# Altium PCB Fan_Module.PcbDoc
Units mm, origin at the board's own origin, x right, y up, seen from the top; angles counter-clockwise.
Board outline 101.5 x 99.19 mm, 2 copper layers (Top Layer, Bottom Layer), stack 1.671 mm thick; 41 components, 31 nets, 143 pads, 0 vias.
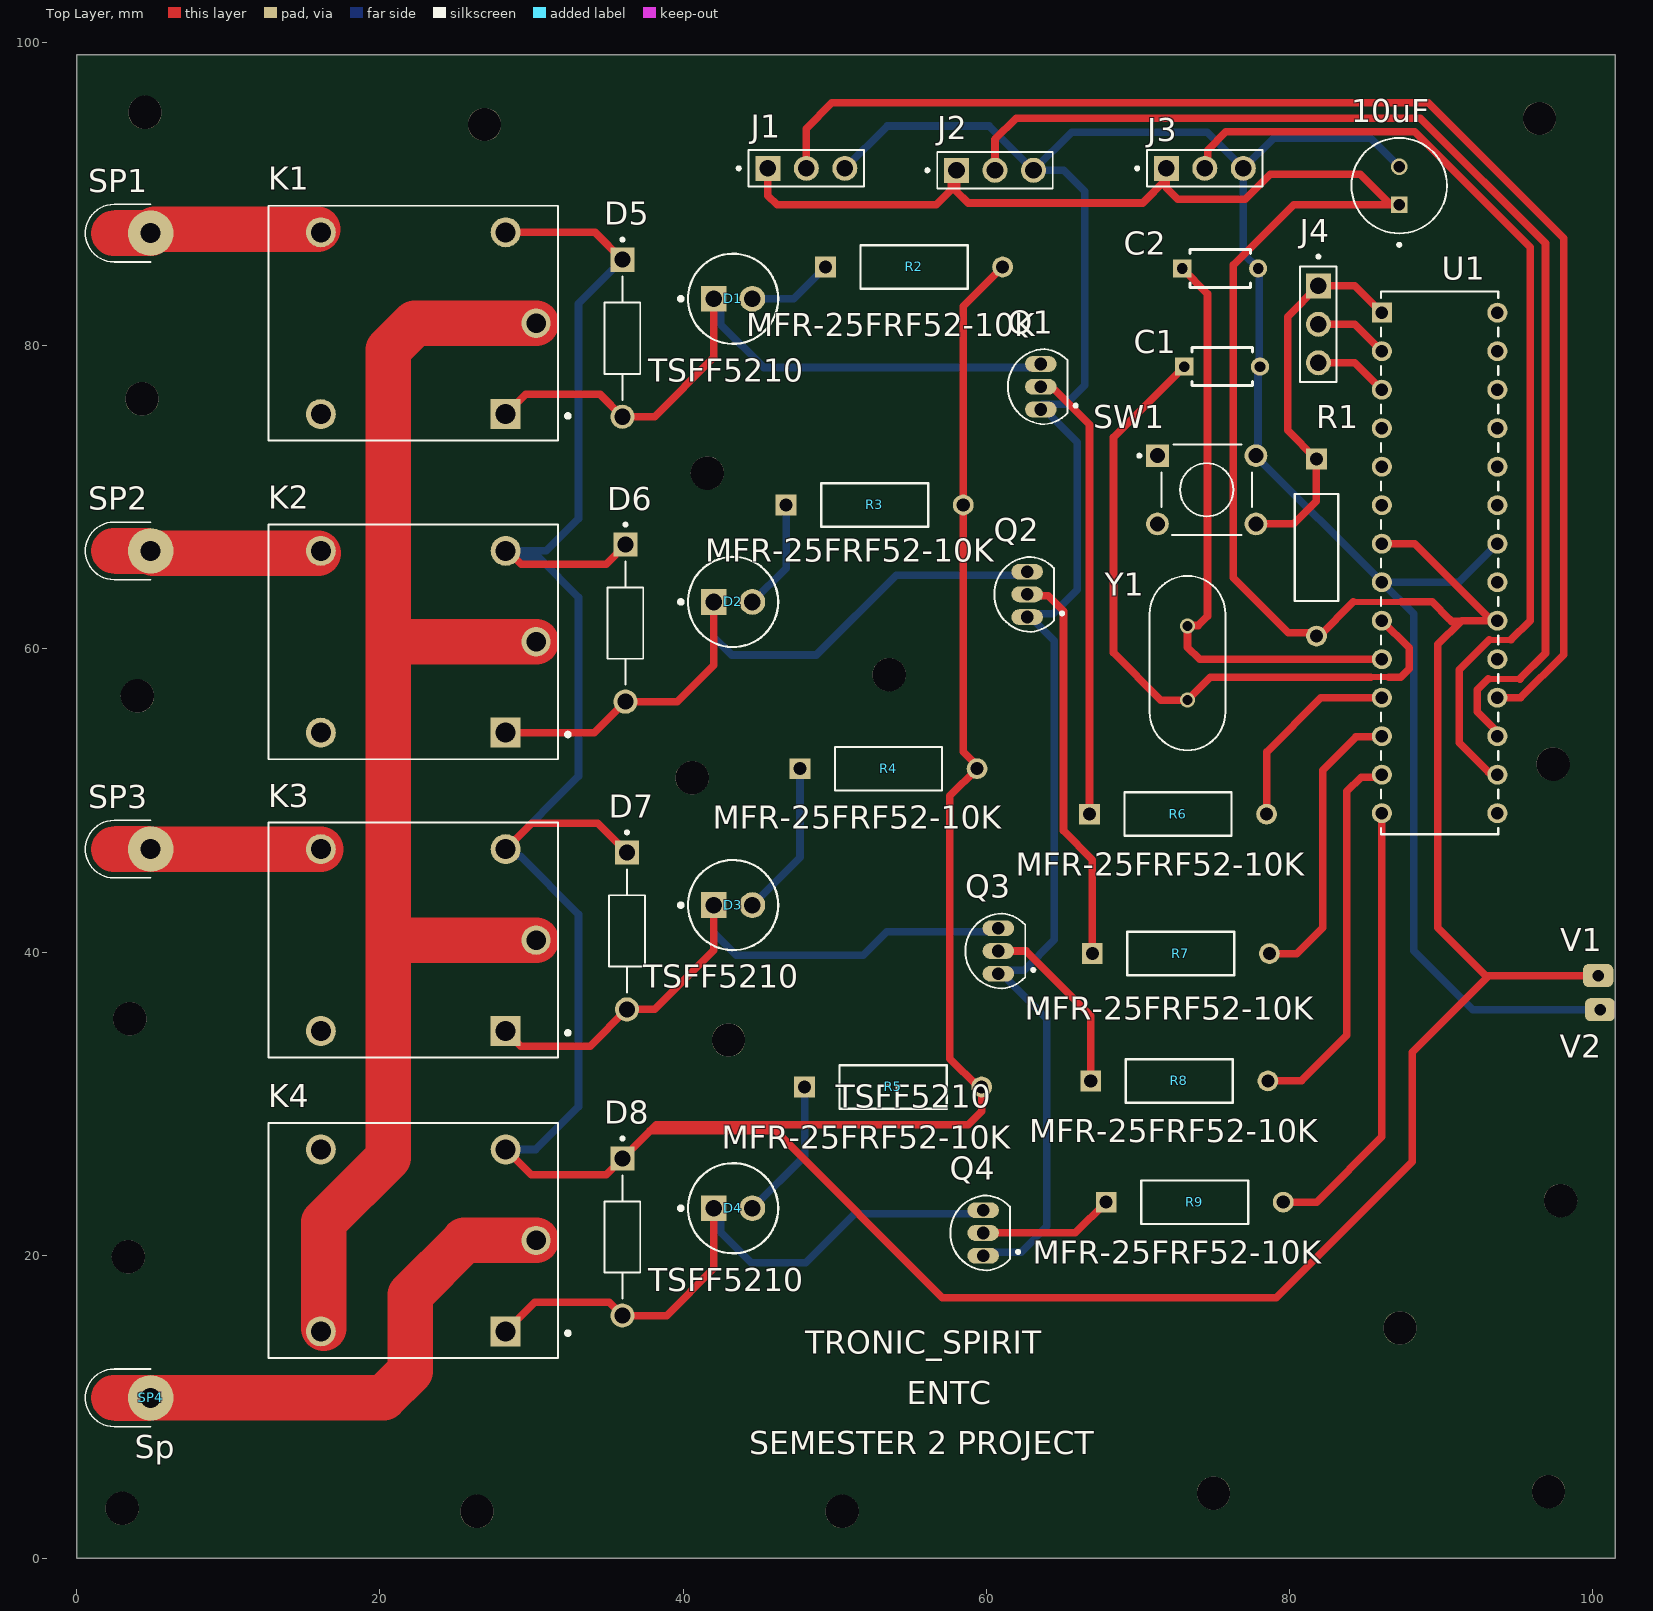
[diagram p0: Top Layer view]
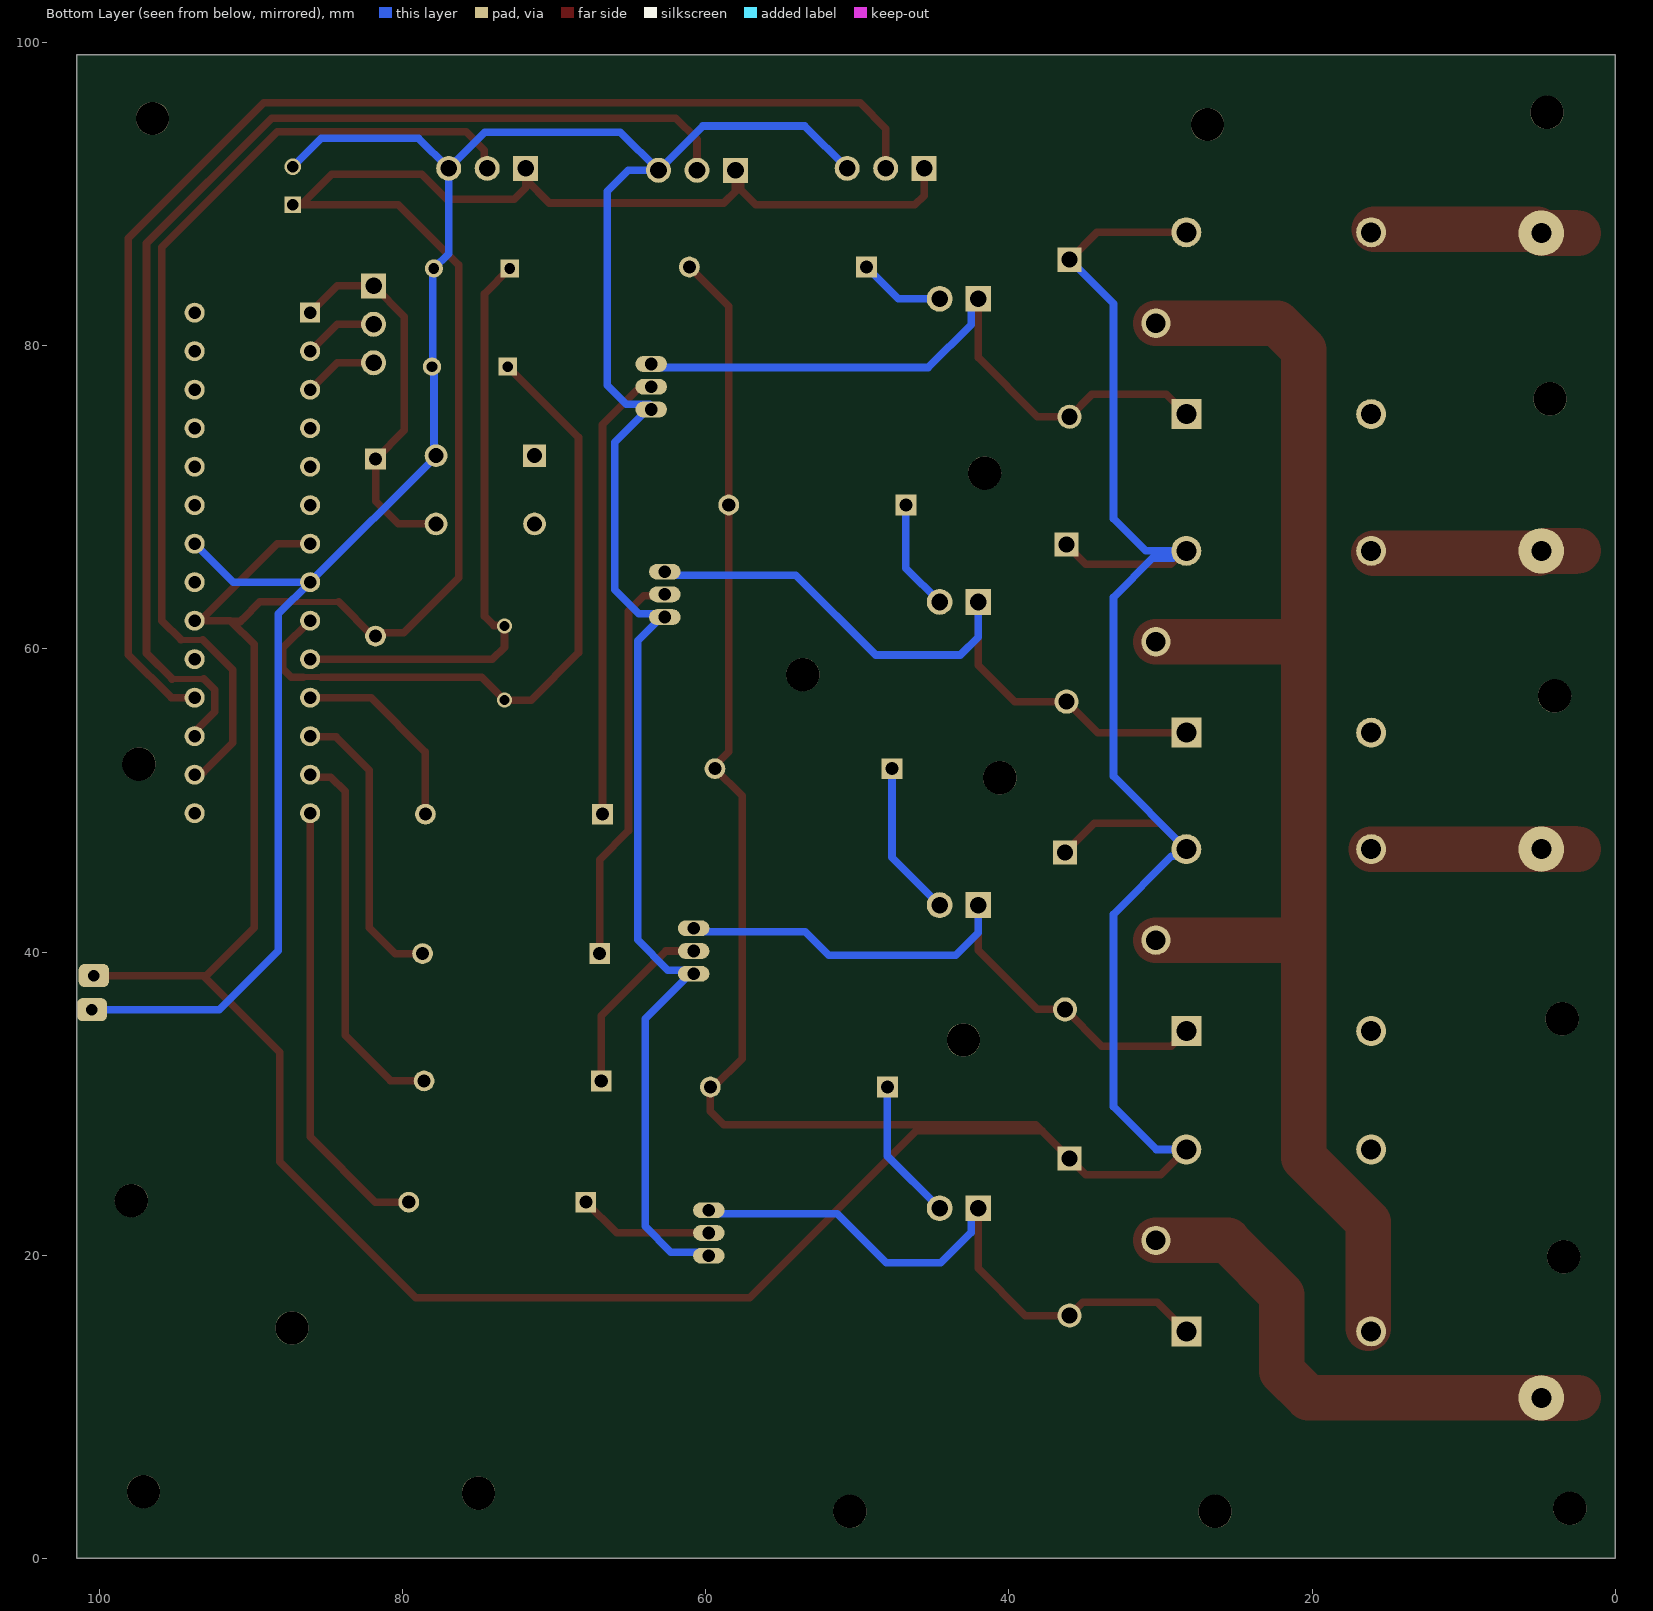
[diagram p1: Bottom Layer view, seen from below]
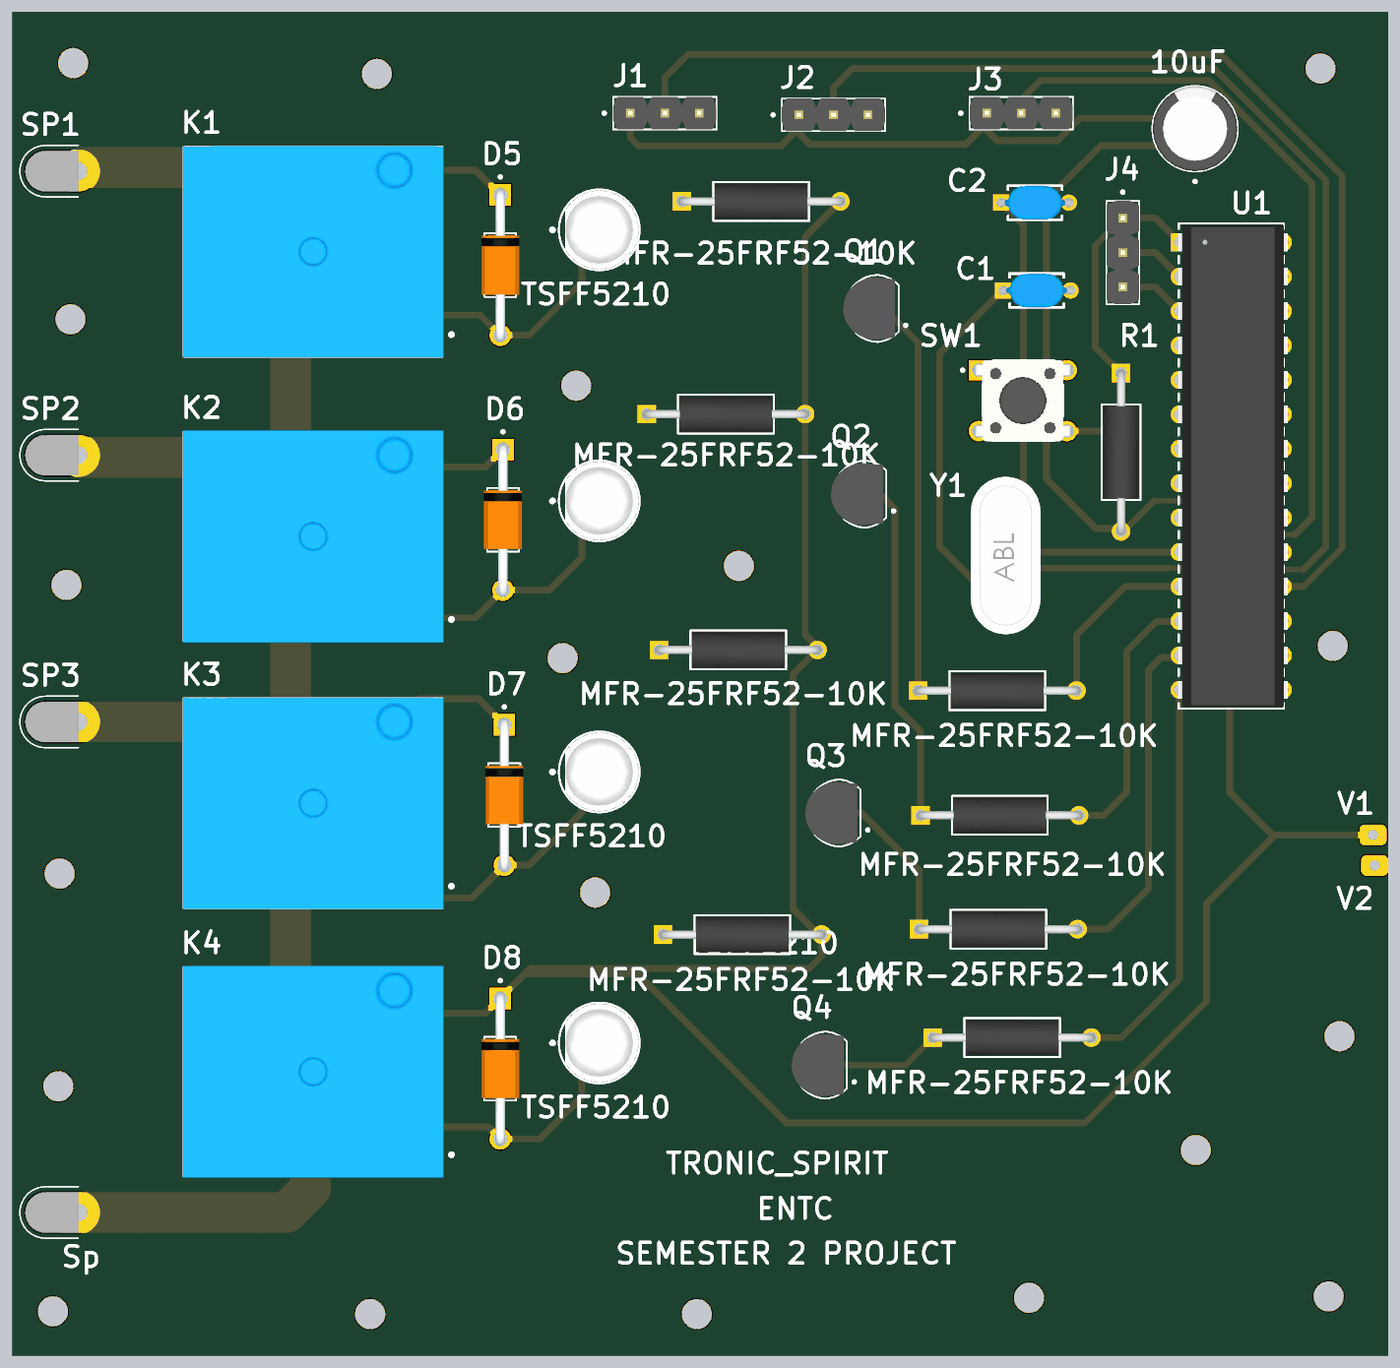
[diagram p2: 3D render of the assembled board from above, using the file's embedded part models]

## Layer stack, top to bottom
Top Solder: solder mask 0.0102, Solder Resist, Dk 3.5
Top Layer: signal copper 0.0356
Dielectric 1: dielectric 1.6, FR-4, Dk 4.8
Bottom Layer: signal copper 0.0356
Bottom Solder: solder mask 0.0102, Solder Resist, Dk 3.5

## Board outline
0,0.013 101.5,0.013 101.5,99.2 0,99.2

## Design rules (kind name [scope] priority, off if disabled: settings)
Clearance [All] p1: gap=0.254 ignorepadtopadclearanceinfootprint=FALSE ismatrix=TRUE
PolygonConnect [All] p1: connectstyle=Relief reliefconductorwidth=0.254 reliefentries=4 polygonreliefangle="90 Angle" airgapwidth=0.254
RoutingVias [All] p1: holewidth=0.711 width=1.27 viastyle="Through Hole" minholewidth=0.711 minwidth=1.27 maxholewidth=0.711 maxwidth=1.27
SilkToSolderMaskClearance [IsPad] p1: minsilkscreentomaskgap=0.1 clearancetoexposedcopper=TRUE
SolderMaskExpansion [All] p1: expansion=0.102 istentingtop=FALSE
SupplyNets "Schematic Supply Nets_1" [InNet('GND')] p1: voltage=0.000
SupplyNets "Schematic Supply Nets" [InNet('+5V')] p2: voltage=0.000
Width [All] p1: maxlimit=0.254 minlimit=0.254 preferedwidth=0.254
29 further rules are at their usual default settings.

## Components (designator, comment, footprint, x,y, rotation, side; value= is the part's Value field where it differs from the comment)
10uF "ECEA1HN100UI" CAPPRD250W50D630H1120 87.249,90.564 r90 top
C1 "RDE5C2A220J0M1H03A" FP-RDE0M1-MFG 75.565,78.626 r0 top
C2 "RDE5C2A220J0M1H03A" FP-RDE0M1-MFG 75.438,85.103 r0 top
D1 "TSFF5210" FP-6_544-5258_09-4-MFG 43.3,83.1 r0 top
D2 "TSFF5210" FP-6_544-5258_09-4-MFG 43.3,63.1 r0 top
D3 "TSFF5210" FP-6_544-5258_09-4-MFG 43.3,43.1 r0 top
D4 "TSFF5210" FP-6_544-5258_09-4-MFG 43.3,23.1 r0 top
D5 "1N4007G" DIOAD1036W78L470D235 36,80.5 r270 top
D6 "1N4007G" DIOAD1036W78L470D235 36.2,61.7 r270 top
D7 "1N4007G" DIOAD1036W78L470D235 36.3,41.4 r270 top
D8 "1N4007G" DIOAD1036W78L470D235 36,21.2 r270 top
J1 "68001-203HLF" AMPHENOL_68001-203HLF 48.133,91.707 r0 top
J2 "68001-203HLF" AMPHENOL_68001-203HLF 60.579,91.58 r0 top
J3 "68001-203HLF" AMPHENOL_68001-203HLF 74.422,91.707 r0 top
J4 "68001-203HLF" AMPHENOL_68001-203HLF 81.915,81.42 r270 top
K1 "SRD-05VDC-SL-C" RELAY_SRD-05VDC-SL-C 22.2,81.49 r180 top
K2 "SRD-05VDC-SL-C" RELAY_SRD-05VDC-SL-C 22.2,60.473 r180 top
K3 "SRD-05VDC-SL-C" RELAY_SRD-05VDC-SL-C 22.2,40.788 r180 top
K4 "ON OFF Switch" RELAY_SRD-05VDC-SL-C 22.2,20.976 r180 top
Q1 "2N3904" TO92127P495H495-3 63.6,77.3 r90 top
Q2 "2N3904" TO92127P495H495-3 62.7,63.6 r90 top
Q3 "2N3904" TO92127P495H495-3 60.8,40.07 r90 top
Q4 "2N3904" TO92127P495H495-3 59.8,21.47 r90 top
R1 "MFR-25FRF52-10K" YAG_MF25_YAG 81.788,72.53 r270 top
R2 "MFR-25FRF52-10K" YAG_MF25_YAG 49.4,85.2 r0 top
R3 "MFR-25FRF52-10K" YAG_MF25_YAG 46.8,69.5 r0 top
R4 "MFR-25FRF52-10K" YAG_MF25_YAG 47.716,52.1 r0 top
R5 "MFR-25FRF52-10K" YAG_MF25_YAG 48.016,31.1 r0 top
R6 "MFR-25FRF52-10K" YAG_MF25_YAG 66.816,49.1 r0 top
R7 "MFR-25FRF52-10K" YAG_MF25_YAG 67,39.9 r0 top
R8 "MFR-25FRF52-10K" YAG_MF25_YAG 66.9,31.5 r0 top
R9 "MFR-25FRF52-10K" YAG_MF25_YAG 67.916,23.5 r0 top
SP1 "Sp" SOLDERPOINT 4.879,87.428 r90 top
SP2 "Sp" SOLDERPOINT 4.879,66.473 r90 top
SP3 "Sp" SOLDERPOINT 4.879,46.788 r90 top
SP4 "Sp" SOLDERPOINT 4.879,10.593 r90 top
SW1 "1825910-6" SW_1825910-6-4 74.549,70.498 r0 top
U1 "ATMEGA328-PU" 28P3_SPDIP28_SP_MCH 86.106,82.182 r0 top
V1 "DC_Pin" DC_PIN 100.376,38.55 r0 top
V2 "DC_Pin" DC_PIN 100.5,36.3 r0 top
Y1 "ABL-16.000MHZ-B2" XTAL_HC49P488W46L1150T500H350 73.279,59.068 r90 top

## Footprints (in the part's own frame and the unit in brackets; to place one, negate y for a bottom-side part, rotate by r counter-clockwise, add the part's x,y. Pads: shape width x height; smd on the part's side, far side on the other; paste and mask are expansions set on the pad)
28P3_SPDIP28_SP_MCH [mil]
  rect 52x52 / inner round 60 / far side rect 52x52 hole 32 paste-99999 mask+0: 1(0,0)
  round 52 / inner round 60 / far side round 52 hole 32 paste-99999 mask+0: 2(0,-100) 3(0,-200) 4(0,-300) 5(0,-400) 6(0,-500) 7(0,-600) 8(0,-700) 9(0,-800) 10(0,-900) 11(0,-1000) 12(0,-1100) 13(0,-1200) 14(0,-1300) 15(300,-1300) 16(300,-1200) 17(300,-1100) 18(300,-1000) 19(300,-900) 20(300,-800) 21(300,-700) 22(300,-600) 23(300,-500) 24(300,-400) 25(300,-300) 26(300,-200) 27(300,-100) 28(300,0)
  silkscreen extent -2,-1355 302,55, body extent -5,-1350 314,50, height 205
AMPHENOL_68001-203HLF [mm]
  rect 1.65x1.65 / inner round 1.65 / far side rect 1.65x1.65 hole 1.1: 01(-2.54,0)
  round 1.65 hole 1.1: 02(0,0) 03(2.54,0)
  silkscreen extent -4.56,-1.2 3.81,1.2, body extent -3.81,-1.2 3.81,1.2, height 8.38
CAPPRD250W50D630H1120 [mm]
  round 1.1 hole 0.75: N(1.25,0)
  rect 1.1x1.1 hole 0.75: P(-1.25,0)
  silkscreen extent -4,-3.15 3.15,3.15, body extent -3.15,-3.15 3.15,3.15, height 11.2
DC_PIN [mm]
  rrect50% 2x1.524 hole 0.762: 0(0,-0.1)
DIOAD1036W78L470D235 [mm]
  round 1.59 hole 1.06: A(5.18,0)
  rect 1.59x1.59 / inner round 1.59 / far side rect 1.59x1.59 hole 1.06: C(-5.18,0)
  silkscreen extent -6.6,-1.17 4.07,1.17, body extent -5.65,-1.4 5.65,1.4, height 2.8
FP-6_544-5258_09-4-MFG [mm]
  rect 1.7x1.7 hole 1.1 paste-2539.97 mask+0: 1(-1.27,0)
  round 1.7 hole 1.1 paste-2539.97 mask+0: 2(1.27,0)
  silkscreen extent -3.57,-2.97 2.98,2.97, body extent -3.08,-3.08 3.08,3.08, height 0.25
FP-RDE0M1-MFG [mm]
  rect 1.2x1.2 hole 0.7 paste-2539.97 mask+0: 1(-2.5,0)
  round 1.2 hole 0.7 paste-2539.97 mask+0: 2(2.5,0)
  silkscreen extent -2,-1.25 2,1.25, body extent -3.2,-1.35 3.2,1.35, height 0.25
RELAY_SRD-05VDC-SL-C [mm]
  rect 1.98x1.98 / inner round 1.98 / far side rect 1.98x1.98 hole 1.32: A1(-6.1,6)
  round 1.98 hole 1.32: A2(-6.1,-6) NC(6.1,6) NO(6.1,-6)
  round 1.935 hole 1.29: COM(-8.1,0)
  silkscreen extent -10.3,-7.75 9.55,7.75, body extent -9.6,-7.8 9.6,7.8, height 15.8
SOLDERPOINT [mm]
  round 3 hole 1.32 paste-2539.97: 0(0,0)
  Top Layer region: -1.5,0 -1.5,2.413 -1.351,3.064 -0.935,3.586 -0.334,3.875 0.334,3.875 0.935,3.586 1.351,3.064 1.5,2.413 1.5,2.413 1.5,0
  silkscreen extent -1.9,0 1.9,4.31
SW_1825910-6-4 [mm]
  rect 1.498x1.498 / inner round 1.498 / far side rect 1.498x1.498 hole 0.99: 1(-3.25,2.25)
  round 1.498 hole 0.99: 2(3.25,2.25) 3(-3.25,-2.25) 4(3.25,-2.25)
  silkscreen extent -4.54,-3 3,3, body extent -3.9,-3 3.9,3, height 5.01
TO92127P495H495-3 [mm]
  oval 1.04x2.08 hole 0.84: 1(-1.5,0) 2(0,0) 3(1.5,0)
  silkscreen extent -2.48,-2.4 2.48,2.16, body extent -2.28,-1.52 2.28,2.31, height 5.44
XTAL_HC49P488W46L1150T500H350 [mm]
  round 1.007 hole 0.657: 1(-2.44,0) 2(2.44,0)
  silkscreen extent -5.75,-2.5 5.75,2.5, body extent -5.75,-2.5 5.75,2.5, height 3.25
YAG_MF25_YAG [mil]
  rect 54x54 / inner round 60 / far side rect 54x54 hole 34 paste-99999 mask+0: 1(0,0)
  round 54 / inner round 60 / far side round 54 hole 34 paste-99999 mask+0: 2(460,0)
  silkscreen extent 91,-56 369,57, body extent -12,-51 472,51, height 103

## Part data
10uF: "CAP ALUM 10UF 20% 50V RADIAL", Package="RADIAL-2 Panasonic"
C1 C2: library part CMP-06035-022985-1, "Ceramic Capacitor 22pF ±5% 100V C0G Radial", Capacitance=22pF, Case/Package=Radial, Dielectric=C0G, Max Operating Temperature=125°C, Min Operating Temperature=-55°C, Package Quantity=1, Resistor Type=Ceramic, Tolerance=5%, Voltage Rating=100V
D1 D2 D3 D4: library part CMP-00030-41223146-1, "TSFF5210 TSFF5210 IR LED, 870nm, T-1 3/4 (5mm) Through Hole package", Case/Package=Radial, Forward Current=100mA, Forward Voltage=1.5V, Max Operating Temperature=85°C, Min Operating Temperature=-40°C, Power Dissipation=180W, Power Rating=250mW, Reverse Voltage=5V
D5 D6 D7 D8: "1A, 1000V, Standard Recovery Rectifier", Package="DO-41 Taiwan Semiconductor"
J1 J2 J3 J4: "BergStik<sup>&reg;</sup>, Board to Board connector, Unshrouded vertical header, Through Hole, Single Row, , 3 Positions, 2.54 mm (0.100in) Pitch.", Package=None
K1 K2 K3: "5V Trigger Relay Module For Arduino And Raspberry Pi 5V Trigger Relay Module For Arduino And Raspberry Pi", Package="NON STANDARD-5 Songle Relay"
K4: library part SRD-05VDC-SL-C, "5V Trigger Relay Module For Arduino And Raspberry Pi 5V Trigger Relay Module For Arduino And Raspberry Pi", Package="NON STANDARD-5 Songle Relay"
Q1 Q2 Q3 Q4: "TRANS NPN 40V 200MA TO92-3", Package="TO-226-3 Rectron"
R1 R2 R3 R4 R5 R6 R7 R8 R9: "No Description Available", Mfr_Name=Yageo
SP1 SP2 SP3 SP4: library part soldPoint
SW1: "Switch Push Button OFF (ON) SPST Round Button 0.05A 24VDC Momentary Contact PC Pins Thru-Hole", Package=None
U1: "No Description Available", Mfr_Name=Microchip
Y1: "HC/49US (AT49) MICROPROCESSOR CRYSTAL", Package="HC-49/US ABRACON"

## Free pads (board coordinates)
  round 2.2 hole 2.2: 2(4.5,95.4) 3(4.3,76.5) 3(97.1,4.4) 4(4,56.9) 5(3.5,35.6) 6(3.4,19.9) 7(3,3.3) 8(40.6,51.5) 9(41.6,71.6) 10(26.9,94.6) 11(96.5,95) 12(97.4,52.4) 13(43,34.2) 14(26.4,3.1) 16(97.9,23.6) 19(50.5,3.1) 20(75,4.3) 21(87.3,15.2) 22(53.6,58.3)

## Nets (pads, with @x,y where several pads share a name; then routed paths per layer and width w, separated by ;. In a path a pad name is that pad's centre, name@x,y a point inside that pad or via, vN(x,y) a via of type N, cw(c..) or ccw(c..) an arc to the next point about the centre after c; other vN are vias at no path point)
+5V: 10uF.P D5.C D6.C D7.C D8.C J1.01 J2.01 J3.01 K1.A2 K2.A2 K3.A2 K4.A2 R1.2 R2.2 R3.2 R4.2 R5.2 U1.7 U1.20 V1.0 | length 410.8
  Top Layer w0.4: 84.22,63.1 87.4,63.1
  Top Layer w0.5: K4.A2 29.976,25.3 34.92,25.3 D8.C 37.82,28.2 ; K3.A2 30.012,48.5 34.38,48.5 D7.C ; K2.A2 28.46,66.473 29.333,65.6 34.92,65.6 D6.C ; K1.A2 34.19,87.49 D5.C ; J1.01 45.593,89.907 46.206,89.294 56.694,89.294 57.698,90.298 57.698,91.005 57.754,91.061 J2.01@58.039,91.061 ; J2.01 J2.01@58.039,91.061 ; R2.2 58.484,82.6 R3.2 58.484,53.215 59.4,52.299 R4.2 57.6,50.3 57.6,32.964 59.464,31.1 R5.2 59.7,29.5 58.8,28.6 38.22,28.6 37.82,28.2 ; J3.01 J3.01@71.882,90.982 ; 84.22,63.1 81.966,60.846 R1.2 81.574,61.06 79.923,61.06 76.3,64.683 76.3,85.33 80.284,89.314 86.686,89.314 ; U1.7 88.258,66.942 93.05,62.15 ; 10uF.P 86.686,89.314 ; 87.4,63.1 89.412,63.1 90.551,61.961 90.574,61.961 90.727,61.808 91.308,61.808 ; 92.9,38.5 89.8,41.6 89.8,60.3 91.308,61.808 ; U1.20 91.362,61.862 91.308,61.808 ; V1.0 93.15,38.45 88.1,33.4 88.1,26.174 79.126,17.2 57.107,17.2 46.107,28.2 37.82,28.2 ; J2.01@58.039,91.061 58.039,90.2 58.818,89.421 70.321,89.421 J3.01@71.882,90.982 ; J3.01@71.882,90.982 71.882,90.437 72.644,89.675 77.089,89.675 78.74,91.326 84.674,91.326 86.686,89.314
  Bottom Layer w0.5: K4.A2 30.276,26.976 33.1,29.8 33.1,42.5 29.286,46.314 29.175,46.314 28.7,46.788 K3.A2 33.1,51.588 33.1,63.407 30.507,66 29.173,66 K2.A2@28.7,66.473 ; K2.A2 K2.A2@28.7,66.473 ; D5.C 33.1,82.78 33.1,68.6 30.973,66.473 K2.A2@28.7,66.473
GND: 10uF.N C1.2 C2.2 J1.03 J2.03 J3.03 Q1.1 Q2.1 Q3.1 Q4.1 SW1.2 U1.8 U1.22 V2.0 | length 208.8
  Bottom Layer w0.5: J1.03 53.466,94.5 60.199,94.5 J2.03 ; Q4.1@59.8,20.2 62.3,20.2 64,21.9 64,35.6 61.423,38.177 61.423,38.551 Q3.1@61.174,38.8 ; Q3.1@60.8,38.8 Q3.1@61.174,38.8 ; Q2.1@62.7,62.33 Q2.1@63.074,62.33 ; 10uF.N 85.363,93.7 78.955,93.7 J3.03 ; U1.22 91.186,64.402 U1.8 ; V2.0 92.1,36.2 88.2,40.1 88.2,62.308 U1.8 ; Q3.1@61.174,38.8 62.5,38.8 64.5,40.8 64.5,60.53 63.323,61.707 63.323,62.081 Q2.1@63.074,62.33 ; Q2.1@63.074,62.33 64.43,62.33 66,63.9 66,73.63 64.223,75.407 64.223,75.781 63.974,76.03 63.6,76.03 63.703,76.133 65.24,76.133 66.5,77.393 66.5,90.2 65.12,91.58 J2.03 ; J2.03 65.639,94.1 74.569,94.1 J3.03 ; J3.03 76.962,86.079 C2.2 78.002,85.039 78.002,78.689 C1.2 77.932,78.493 77.932,72.881 SW1.2 77.799,72.728 86.106,64.421 U1.8
NetC1_1: C1.1 U1.9 Y1.1 | length 46.4
  Top Layer w0.4: 85.358,58.142 86.573,58.142
  Top Layer w0.5: C1.1 68.4,73.961 68.4,59.756 71.528,56.628 Y1.1 74.793,58.142 85.358,58.142 ; U1.9 87.9,60.068 87.9,58.7 87.342,58.142 86.573,58.142
NetC2_1: C2.1 U1.10 Y1.2 | length 39.8
  Top Layer w0.5: C2.1 74.6,83.441 74.6,62.167 73.981,61.548 73.319,61.548 Y1.2 73.279,60.121 74.078,59.322 U1.10
NetD1_1: D1.1 D5.A K1.A1 Q1.3 | length 44.5
  Top Layer w0.5: K1.A1 29.61,76.8 34.52,76.8 D5.A 38.12,75.32 42.03,79.23 D1.1
  Bottom Layer w0.5: D1.1 42.5,82.63 42.5,81.4 45.33,78.57 Q1.3@63.6,78.57
NetD1_2: D1.2 R2.1 | length 5.7
  Bottom Layer w0.5: D1.2 47.3,83.1 R2.1
NetD2_1: D2.1 D6.A K2.A1 Q2.3 | length 45.4
  Top Layer w0.5: K2.A1 34.153,54.473 D6.A 39.62,56.52 42.03,58.93 D2.1
  Bottom Layer w0.5: D2.1 42.03,60.77 43.2,59.6 48.8,59.6 54.07,64.87 Q2.3@62.7,64.87
NetD2_2: D2.2 R3.1 | length 7.3
  Bottom Layer w0.5: D2.2 46.8,65.33 R3.1
NetD3_1: D3.1 D7.A K3.A1 Q3.3 | length 41.6
  Top Layer w0.5: K3.A1 29.288,33.8 33.88,33.8 D7.A 38.12,36.22 42.03,40.13 D3.1
  Bottom Layer w0.5: D3.1 42.03,41.27 43.5,39.8 51.9,39.8 53.44,41.34 Q3.3@60.8,41.34
NetD3_2: D3.2 R4.1 | length 10.3
  Bottom Layer w0.5: D3.2 47.716,46.246 R4.1
NetD4_1: D4.1 D8.A K4.A1 Q4.3 | length 41.4
  Top Layer w0.5: K4.A1 30.224,16.9 35.12,16.9 D8.A 38.92,16.02 42.03,19.13 D4.1
  Bottom Layer w0.5: D4.1 42.5,22.63 42.5,21.5 44.5,19.5 48.1,19.5 51.34,22.74 Q4.3@59.8,22.74
NetD4_2: D4.2 R5.1 | length 9.4
  Bottom Layer w0.5: D4.2 48.016,26.546 R5.1
NetJ4_02: J4.02 U1.2 | length 4.9
  Top Layer w0.5: J4.02 84.328,81.42 U1.2
NetJ4_03: J4.03 U1.3 | length 4.9
  Top Layer w0.5: J4.03 84.328,78.88 U1.3
NetK1_COM: K1.COM K2.COM K3.COM K4.NC | length 96.9
  Top Layer w3: K4.NC@16.3,15.176 16.3,22.192 20.54,26.432 20.54,39.93 ; K3.COM 21.398,40.788 20.54,39.93 ; K2.COM 21.017,60.473 20.54,59.996 ; K1.COM 22.298,81.49 20.54,79.733 20.54,59.996 ; 20.54,39.93 20.54,59.996
NetK1_NO: K1.NO SP1.0 | length 11.2
  Top Layer w3: SP1.0@4.941,87.49 SP1.0 5.151,87.7 K1.NO@15.89,87.7
NetK2_NO: K2.NO SP2.0 | length 10.9
  Top Layer w3: SP2.0@5.052,66.3 K2.NO@15.927,66.3
NetK3_NO: K3.NO SP3.0 | length 11.2
  Top Layer w3: SP3.0 K3.NO
NetK4_COM: K4.COM SP4.0 | length 32.7
  Top Layer w3: SP4.0 20.243,10.593 22,12.35 22,17.4 25.576,20.976 K4.COM
NetQ1_2: Q1.2 R6.1 | length 29.9
  Top Layer w0.5: Q1.2 64.266,77.3 64.512,77.054 64.544,77.054 66.816,74.782 R6.1
NetQ2_2: Q2.2 R7.1 | length 26.2
  Top Layer w0.5: Q2.2 62.803,63.497 64.101,63.497 65.1,62.498 65.1,48 67,46.1 R7.1
NetQ3_2: Q3.2 R8.1 | length 12.2
  Top Layer w0.5: Q3.2 62.63,40.07 66.9,35.8 R8.1
NetQ4_2: Q4.2 R9.1 | length 9
  Top Layer w0.5: Q4.2 65.886,21.47 R9.1
PIR_01: J1.02 U1.18 | length 90
  Top Layer w0.5: J1.02 48.133,94.333 49.825,96.025 89.154,96.025 98.1,87.079 98.1,59.632 95.25,56.782 U1.18
PIR_02: J2.02 U1.17 | length 78.5
  Top Layer w0.4: 93.118,58.018 95.216,58.018
  Top Layer w0.5: J2.02 60.579,93.612 61.976,95.009 88.646,95.009 96.9,86.755 96.9,59.702 95.216,58.018 ; 93.118,58.018 92.4,57.3 92.4,55.857 93.726,54.531 U1.17
RELAY_01: R6.2 U1.11 | length 13.2
  Top Layer w0.5: R6.2 78.5,53.2 82.082,56.782 U1.11
RELAY_02: R7.2 U1.12 | length 19.5
  Top Layer w0.5: R7.2 80.5,39.9 82.2,41.6 82.2,52 84.4,54.2 86.064,54.2 U1.12
RELAY_03: R8.2 U1.13 | length 25.3
  Top Layer w0.5: R8.2 80.8,31.5 83.8,34.5 83.8,50.6 84.745,51.545 85.949,51.545 U1.13
RELAY_04: R9.2 U1.14 | length 29.6
  Top Layer w0.5: R9.2 81.8,23.5 86.106,27.806 U1.14
SWITCH: J4.01 R1.1 SW1.4 U1.1 | length 25.4
  Top Layer w0.5: SW1.4 80.3,68.248 81.788,69.736 R1.1 79.883,74.435 79.883,81.928 J4.01 84.328,83.96 U1.1
TEMP: J3.02 U1.16 | length 65.1
  Top Layer w0.4: 93.182,60.6 94.623,60.6
  Top Layer w0.5: J3.02 74.612,91.897 74.612,92.913 75.819,94.12 88.265,94.12 95.885,86.5 95.885,61.862 94.623,60.6 ; 93.182,60.6 91.2,58.618 91.2,53.8 93.141,51.859 93.569,51.859 U1.16
pads on no net: K1.NC K2.NC K3.NC K4.NO SW1.1 SW1.3 U1.4 U1.5 U1.6 U1.15 U1.19 U1.21 U1.23 U1.24 U1.25 U1.26 U1.27 U1.28

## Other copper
Top Layer:

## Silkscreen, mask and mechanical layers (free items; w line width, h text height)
Top Overlay:
  text "TRONIC_SPIRIT" at 48.054,13.508 h1.52
  text "ENTC" at 54.754,10.154 h1.52
  text "SEMESTER 2 PROJECT" at 44.354,6.854 h1.52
